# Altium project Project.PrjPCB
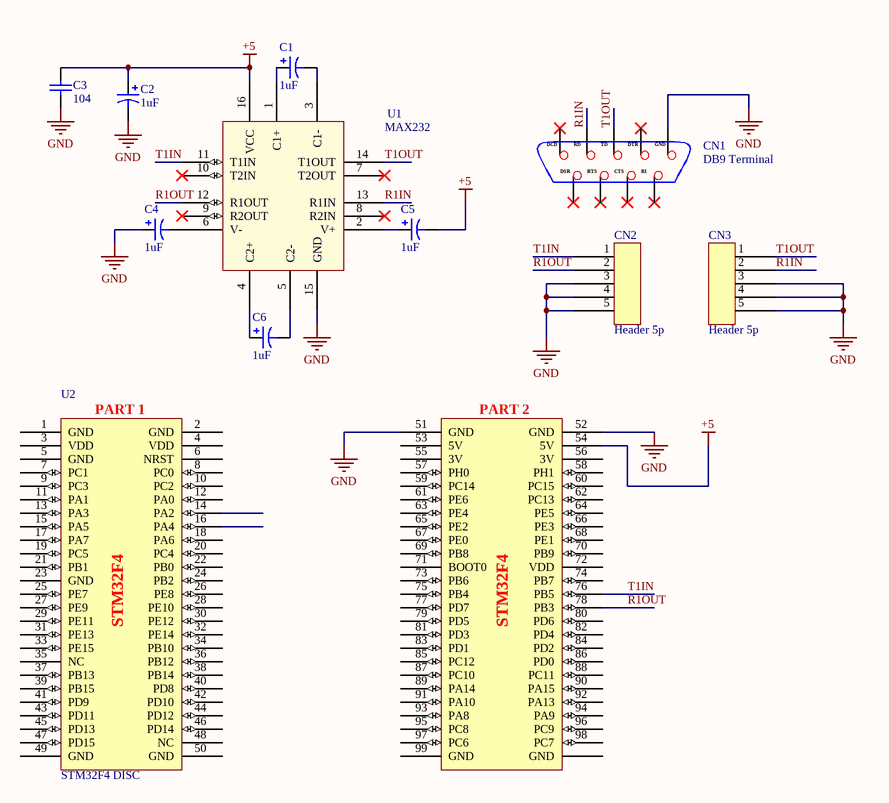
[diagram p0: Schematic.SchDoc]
1 sheet, 11 parts. Net scope: global (net labels, ports and power ports of the same name join across sheets).
Board file: PCB1.PcbDoc

## Sheet Schematic.SchDoc
size A

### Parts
C1  1uF  [TU HOA 3MM]
C2  1uF  [TU HOA 3MM]
C3  104  [tu 0805]
C4  1uF  [TU HOA 3MM]
C5  1uF  [TU HOA 3MM]
C6  1uF  [TU HOA 3MM]
CN1  DB9 Terminal  [DB9]
CN2  Header 5p  [HEADER 5P MALE]
CN3  Header 5p  [HEADER 5P MALE]
U1  MAX232  [DIP16]
U2  STM32F4 DISC  [STM32F4 DISC]

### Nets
+5: C2.1 C3.2 C5.2 U1.16(VCC) U2.54(5V)
GND: C2.2 C3.1 C4.1 CN1.5(GND) CN2.3 CN2.4 CN2.5 CN3.3 CN3.4 CN3.5 U1.15(GND) U2.51(GND) U2.52(GND)
R1IN: CN1.2(RD) CN3.2 U1.13(R1IN)
R1OUT: CN2.2 U1.12(R1OUT) U2.78(PB3)
T1IN: CN2.1 U1.11(T1IN) U2.76(PB5)
T1OUT: CN1.3(TD) CN3.1 U1.14(T1OUT)
NetC1_1: C1.1 U1.1(C1+)
NetC1_2: C1.2 U1.3(C1-)
NetC4_2: C4.2 U1.6(V-)
NetC5_1: C5.1 U1.2(V+)
NetC6_1: C6.1 U1.4(C2+)
NetC6_2: C6.2 U1.5(C2-)

Not connected (* = marked no-connect by the designer): CN1 1(DCD)* 4(DTR)* 6(DSR)* 7(RTS)* 8(CTS)* 9(RI)*; U1 7(T2OUT)* 8(R2IN)* 9(R2OUT)* 10(T2IN)*; U2 1(GND) 2(GND) 3(VDD) 4(VDD) 5(GND) 6(NRST) 7(PC1) 8(PC0) 9(PC3) 10(PC2) 11(PA1) 12(PA0) 13(PA3) 14(PA2) 15(PA5) 16(PA4) 17(PA7) 18(PA6) 19(PC5) 20(PC4) 21(PB1) 22(PB0) 23(GND) 24(PB2) 25(PE7) 26(PE8) 27(PE9) 28(PE10) 29(PE11) 30(PE12) 31(PE13) 32(PE14) 33(PE15) 34(PB10) 35(NC) 36(PB12) 37(PB13) 38(PB14) 39(PB15) 40(PD8) 41(PD9) 42(PD10) 43(PD11) 44(PD12) 45(PD13) 46(PD14) 47(PD15) 48(NC) 49(GND) 50(GND) 53(5V) 55(3V) 56(3V) 57(PH0) 58(PH1) 59(PC14) 60(PC15) 61(PE6) 62(PC13) 63(PE4) 64(PE5) 65(PE2) 66(PE3) 67(PE0) 68(PE1) 69(PB8) 70(PB9) 71(BOOT0) 72(VDD) 73(PB6) 74(PB7) 75(PB4) 77(PD7) 79(PD5) 80(PD6) 81(PD3) 82(PD4) 83(PD1) 84(PD2) 85(PC12) 86(PD0) 87(PC10) 88(PC11) 89(PA14) 90(PA15) 91(PA10) 92(PA13) 93(PA8) 94(PA9) 95(PC8) 96(PC9) 97(PC6) 98(PC7) 99(GND) ?1(GND)

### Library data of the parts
C1 C2 C4-C6 = Tu 3mm: Cắm
C3 = Tu 0805 104 50V 10%: Dán; Don_Vi: Con; So_Chan: 2; Ten_Linh_Kien: Tụ 0805 104-100nF 10% 50V; Ma_Hang: MH004551
U2 = STM32F4 DISC: STM32F4 Discovery board. Chip on Board is Stm32f411VET6. Speed is 150MHz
